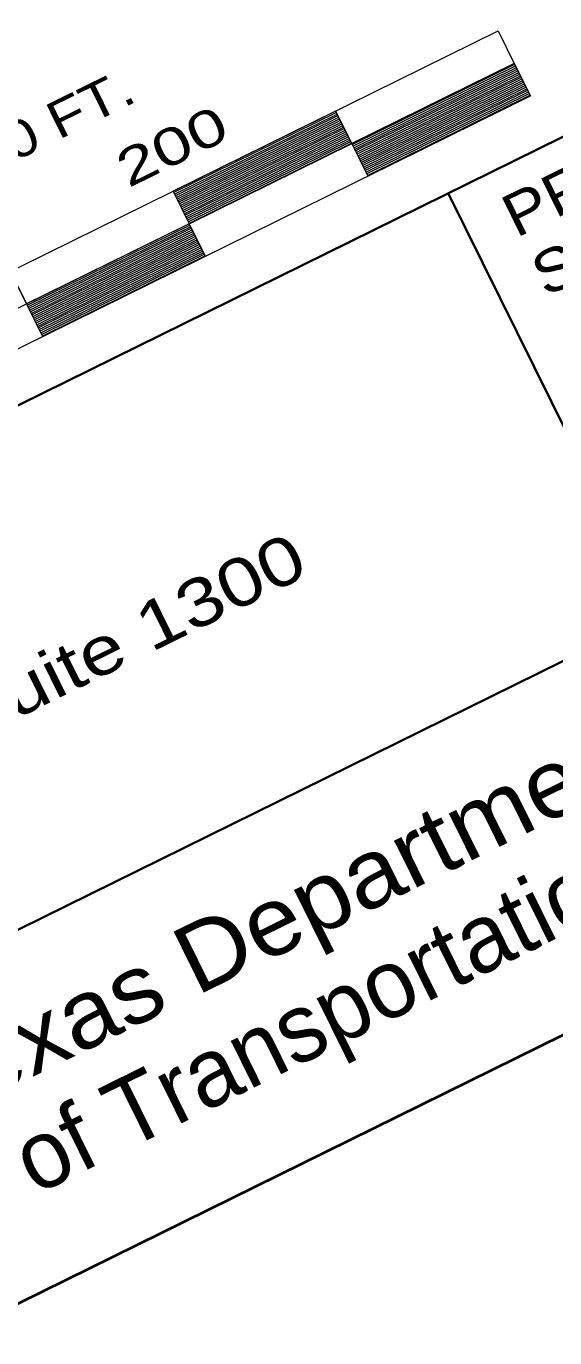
# Model space of a CAD drawing. Extents: x 2356606 to 2371222, y 6973096 to 6982644.
# Drawn here: x 2358383.7 to 2358529.4, y 6973288.2 to 6973650.2 of the extents above; entities that cross this region are included whole.
import ezdxf
from ezdxf.enums import TextEntityAlignment as Align

# ---------------------------------------------------------------- set-up
doc = ezdxf.new("R2010")
doc.units = 0
doc.header["$LTSCALE"] = 2
doc.layers.add('62', color=7, linetype='Continuous', lineweight=13)
doc.layers.add('63', color=7, linetype='Continuous', lineweight=13)

msp = doc.modelspace()

# ---------------------------------------------------------------- linework, layer by layer
at = {"layer": '62', "lineweight": 40}
msp.add_line((2370869.698, 6979460.986), (2358244.847, 6973230.201), dxfattribs=at)
at = {"layer": '62', "lineweight": 35}
for p, q in [((2358728.863, 6973716.998), (2358145.069, 6973428.875)), ((2358597.83, 6973405.896), (2358500.028, 6973604.06)), ((2358557.461, 6973487.691), (2358202.501, 6973312.506))]:
    msp.add_line(p, q, dxfattribs=at)
at = {"layer": '62'}
for p, q in [((2358155.076, 6973471.825), (2358513.803, 6973648.869)), ((2358513.803, 6973648.869), (2358518.229, 6973639.901)), ((2358159.503, 6973462.857), (2358518.229, 6973639.901)), ((2358473.506, 6973617.531), (2358518.347, 6973639.66)), ((2358473.728, 6973617.082), (2358518.568, 6973639.212)), ((2358473.948, 6973616.633), (2358518.79, 6973638.764)), ((2358474.169, 6973616.185), (2358519.011, 6973638.315)), ((2358474.39, 6973615.738), (2358519.232, 6973637.867)), ((2358518.229, 6973639.901), (2358522.655, 6973630.932)), ((2358474.612, 6973615.288), (2358519.453, 6973637.419)), ((2358474.833, 6973614.84), (2358519.674, 6973636.971)), ((2358475.054, 6973614.392), (2358519.896, 6973636.523)), ((2358475.277, 6973613.944), (2358520.117, 6973636.074)), ((2358475.498, 6973613.495), (2358520.338, 6973635.626)), ((2358475.719, 6973613.047), (2358520.56, 6973635.177)), ((2358475.94, 6973612.598), (2358520.782, 6973634.729)), ((2358476.16, 6973612.149), (2358521.003, 6973634.281)), ((2358476.382, 6973611.701), (2358521.223, 6973633.832)), ((2358476.604, 6973611.252), (2358521.445, 6973633.384)), ((2358476.825, 6973610.804), (2358521.666, 6973632.934)), ((2358477.046, 6973610.355), (2358521.888, 6973632.486)), ((2358477.268, 6973609.907), (2358522.11, 6973632.038)), ((2358477.49, 6973609.459), (2358522.33, 6973631.589)), ((2358477.711, 6973609.011), (2358522.552, 6973631.141)), ((2358424.295, 6973604.257), (2358469.134, 6973626.387)), ((2358424.516, 6973603.808), (2358469.357, 6973625.938)), ((2358424.738, 6973603.36), (2358469.577, 6973625.489)), ((2358424.958, 6973602.912), (2358469.799, 6973625.042)), ((2358425.179, 6973602.463), (2358470.02, 6973624.592)), ((2358425.401, 6973602.014), (2358470.241, 6973624.144)), ((2358425.623, 6973601.566), (2358470.463, 6973623.696)), ((2358425.843, 6973601.117), (2358470.684, 6973623.248)), ((2358468.961, 6973626.738), (2358473.387, 6973617.77)), ((2358426.065, 6973600.669), (2358470.905, 6973622.799)), ((2358426.287, 6973600.221), (2358471.127, 6973622.35)), ((2358426.507, 6973599.772), (2358471.349, 6973621.902)), ((2358426.729, 6973599.324), (2358471.57, 6973621.455)), ((2358426.95, 6973598.876), (2358471.79, 6973621.006)), ((2358427.172, 6973598.428), (2358472.011, 6973620.558)), ((2358427.392, 6973597.979), (2358472.233, 6973620.109)), ((2358427.614, 6973597.531), (2358472.455, 6973619.661)), ((2358427.836, 6973597.083), (2358472.676, 6973619.214)), ((2358428.056, 6973596.634), (2358472.896, 6973618.764)), ((2358428.278, 6973596.186), (2358473.119, 6973618.316)), ((2358428.5, 6973595.738), (2358473.339, 6973617.867)), ((2358473.387, 6973617.77), (2358477.813, 6973608.801)), ((2358424.122, 6973604.608), (2358428.548, 6973595.64)), ((2358383.879, 6973573.158), (2358428.719, 6973595.288)), ((2358384.101, 6973572.71), (2358428.941, 6973594.84)), ((2358384.321, 6973572.261), (2358429.163, 6973594.392)), ((2358428.548, 6973595.64), (2358432.973, 6973586.672)), ((2358384.543, 6973571.813), (2358429.385, 6973593.944)), ((2358384.765, 6973571.365), (2358429.605, 6973593.495)), ((2358384.985, 6973570.916), (2358429.826, 6973593.048)), ((2358385.206, 6973570.468), (2358430.048, 6973592.6)), ((2358385.428, 6973570.019), (2358430.269, 6973592.151)), ((2358385.649, 6973569.571), (2358430.491, 6973591.703)), ((2358385.871, 6973569.123), (2358430.712, 6973591.253)), ((2358386.092, 6973568.674), (2358430.932, 6973590.806)), ((2358386.314, 6973568.226), (2358431.155, 6973590.358)), ((2358386.535, 6973567.777), (2358431.375, 6973589.908)), ((2358386.757, 6973567.328), (2358431.598, 6973589.459)), ((2358386.977, 6973566.88), (2358431.818, 6973589.011)), ((2358387.198, 6973566.432), (2358432.04, 6973588.562)), ((2358387.42, 6973565.983), (2358432.261, 6973588.115)), ((2358387.641, 6973565.535), (2358432.482, 6973587.666)), ((2358387.863, 6973565.087), (2358432.704, 6973587.218)), ((2358388.084, 6973564.64), (2358432.925, 6973586.769)), ((2358379.28, 6973582.477), (2358383.706, 6973573.509)), ((2358383.706, 6973573.509), (2358388.132, 6973564.54))]:
    msp.add_line(p, q, dxfattribs=at)
for points in [[(2358477.813, 6973608.801), (2358522.655, 6973630.932), (2358518.229, 6973639.901), (2358473.387, 6973617.77)], [(2358428.548, 6973595.64), (2358473.387, 6973617.77), (2358468.961, 6973626.738), (2358424.122, 6973604.608)], [(2358388.132, 6973564.54), (2358432.973, 6973586.672), (2358428.548, 6973595.64), (2358383.706, 6973573.509)], [(2358338.865, 6973551.378), (2358383.706, 6973573.509), (2358379.28, 6973582.477), (2358334.439, 6973560.347)]]:
    msp.add_lwpolyline(points, close=True, dxfattribs=at)
at = {"layer": '63', "lineweight": 40}
msp.add_line((2370869.698, 6979460.986), (2358244.847, 6973230.201), dxfattribs=at)
at = {"layer": '63'}
for p, q in [((2358155.076, 6973471.825), (2358513.803, 6973648.869)), ((2358513.803, 6973648.869), (2358518.229, 6973639.901)), ((2358159.503, 6973462.857), (2358518.229, 6973639.901)), ((2358473.506, 6973617.531), (2358518.347, 6973639.66)), ((2358473.728, 6973617.082), (2358518.568, 6973639.212)), ((2358473.948, 6973616.633), (2358518.79, 6973638.764)), ((2358474.169, 6973616.185), (2358519.011, 6973638.315)), ((2358474.39, 6973615.738), (2358519.232, 6973637.867)), ((2358518.229, 6973639.901), (2358522.655, 6973630.932)), ((2358474.612, 6973615.288), (2358519.453, 6973637.419)), ((2358474.833, 6973614.84), (2358519.674, 6973636.971)), ((2358475.054, 6973614.392), (2358519.896, 6973636.523)), ((2358475.277, 6973613.944), (2358520.117, 6973636.074)), ((2358475.498, 6973613.495), (2358520.338, 6973635.626)), ((2358475.719, 6973613.047), (2358520.56, 6973635.177)), ((2358475.94, 6973612.598), (2358520.782, 6973634.729)), ((2358476.16, 6973612.149), (2358521.003, 6973634.281)), ((2358163.928, 6973453.889), (2358522.655, 6973630.932)), ((2358476.382, 6973611.701), (2358521.223, 6973633.832)), ((2358476.604, 6973611.252), (2358521.445, 6973633.384)), ((2358476.825, 6973610.804), (2358521.666, 6973632.934)), ((2358477.046, 6973610.355), (2358521.888, 6973632.486)), ((2358477.268, 6973609.907), (2358522.11, 6973632.038)), ((2358477.49, 6973609.459), (2358522.33, 6973631.589)), ((2358477.711, 6973609.011), (2358522.552, 6973631.141)), ((2358424.295, 6973604.257), (2358469.134, 6973626.387)), ((2358424.516, 6973603.808), (2358469.357, 6973625.938)), ((2358424.738, 6973603.36), (2358469.577, 6973625.489)), ((2358424.958, 6973602.912), (2358469.799, 6973625.042)), ((2358425.179, 6973602.463), (2358470.02, 6973624.592)), ((2358425.401, 6973602.014), (2358470.241, 6973624.144)), ((2358425.623, 6973601.566), (2358470.463, 6973623.696)), ((2358425.843, 6973601.117), (2358470.684, 6973623.248)), ((2358468.961, 6973626.738), (2358473.387, 6973617.77)), ((2358426.065, 6973600.669), (2358470.905, 6973622.799)), ((2358426.287, 6973600.221), (2358471.127, 6973622.35)), ((2358426.507, 6973599.772), (2358471.349, 6973621.902)), ((2358426.729, 6973599.324), (2358471.57, 6973621.455)), ((2358426.95, 6973598.876), (2358471.79, 6973621.006)), ((2358427.172, 6973598.428), (2358472.011, 6973620.558)), ((2358427.392, 6973597.979), (2358472.233, 6973620.109)), ((2358427.614, 6973597.531), (2358472.455, 6973619.661)), ((2358427.836, 6973597.083), (2358472.676, 6973619.214)), ((2358428.056, 6973596.634), (2358472.896, 6973618.764)), ((2358428.278, 6973596.186), (2358473.119, 6973618.316)), ((2358428.5, 6973595.738), (2358473.339, 6973617.867)), ((2358473.387, 6973617.77), (2358477.813, 6973608.801)), ((2358424.122, 6973604.608), (2358428.548, 6973595.64)), ((2358383.879, 6973573.158), (2358428.719, 6973595.288)), ((2358384.101, 6973572.71), (2358428.941, 6973594.84)), ((2358384.321, 6973572.261), (2358429.163, 6973594.392)), ((2358428.548, 6973595.64), (2358432.973, 6973586.672)), ((2358384.543, 6973571.813), (2358429.385, 6973593.944)), ((2358384.765, 6973571.365), (2358429.605, 6973593.495)), ((2358384.985, 6973570.916), (2358429.826, 6973593.048)), ((2358385.206, 6973570.468), (2358430.048, 6973592.6)), ((2358385.428, 6973570.019), (2358430.269, 6973592.151)), ((2358385.649, 6973569.571), (2358430.491, 6973591.703)), ((2358385.871, 6973569.123), (2358430.712, 6973591.253)), ((2358386.092, 6973568.674), (2358430.932, 6973590.806)), ((2358386.314, 6973568.226), (2358431.155, 6973590.358)), ((2358386.535, 6973567.777), (2358431.375, 6973589.908)), ((2358386.757, 6973567.328), (2358431.598, 6973589.459)), ((2358386.977, 6973566.88), (2358431.818, 6973589.011)), ((2358387.198, 6973566.432), (2358432.04, 6973588.562)), ((2358387.42, 6973565.983), (2358432.261, 6973588.115)), ((2358387.641, 6973565.535), (2358432.482, 6973587.666)), ((2358387.863, 6973565.087), (2358432.704, 6973587.218)), ((2358388.084, 6973564.64), (2358432.925, 6973586.769)), ((2358379.28, 6973582.477), (2358383.706, 6973573.509)), ((2358383.706, 6973573.509), (2358388.132, 6973564.54))]:
    msp.add_line(p, q, dxfattribs=at)
for points in [[(2358477.813, 6973608.801), (2358522.655, 6973630.932), (2358518.229, 6973639.901), (2358473.387, 6973617.77)], [(2358428.548, 6973595.64), (2358473.387, 6973617.77), (2358468.961, 6973626.738), (2358424.122, 6973604.608)], [(2358388.132, 6973564.54), (2358432.973, 6973586.672), (2358428.548, 6973595.64), (2358383.706, 6973573.509)], [(2358338.865, 6973551.378), (2358383.706, 6973573.509), (2358379.28, 6973582.477), (2358334.439, 6973560.347)]]:
    msp.add_lwpolyline(points, close=True, dxfattribs=at)

# ---------------------------------------------------------------- texts
at = {"layer": '62'}
for s, height, width, p in [('DIRECT CONNECTOR & RAMP DESIGN SPEED = 50 MPH', 10.2, 1.2, (2358381.426, 6973718.525)), ('FRONTAGE ROAD DESIGN SPEED VARIABLE 35 TO 40 MPH', 10.2, 1.25, (2358399.194, 6973684.505)), ('RAMP DESIGN SPEED VARIABLE 40 TO 50 MPH', 10.2, 1.25, (2358390.532, 6973700.074)), ('SCALE:  1 INCH = 100 FT.', 10.2, 1.2, (2358326.677, 6973586.227)), ('200', 10.2, 1.4, (2358426.095, 6973612.487)), ('Texas Department', 18.76, 1.1, (2358458.09, 6973396.009))]:
    msp.add_text(s, height=height, rotation=26.268, dxfattribs=dict(at, width=width)).set_placement(p, align=Align.CENTER)
for s, height, width, p in [('PRELIMINARY PLAN', 11.74, 1.15, (2358518.728, 6973591.634)), ('SUBMITTAL FOR', 11.74, 1.15, (2358526.802, 6973575.276)), ('3010 LBJ Freeway, Suite 1300', 13.22, 1.25, (2358191.148, 6973365.269))]:
    msp.add_text(s, height=height, rotation=26.268, dxfattribs=dict(at, width=width)).set_placement(p)
msp.add_text('of Transportation', height=18.76, rotation=26.268, dxfattribs=at).set_placement((2358471.15, 6973369.388), align=Align.CENTER)
at = {"layer": '63'}
for s, height, width, p in [('DIRECT CONNECTOR & RAMP DESIGN SPEED = 50 MPH', 10.2, 1.2, (2358381.426, 6973718.525)), ('200', 10.2, 1.4, (2358426.095, 6973612.487)), ('Texas Department', 18.76, 1.1, (2358458.09, 6973396.009))]:
    msp.add_text(s, height=height, rotation=26.268, dxfattribs=dict(at, width=width)).set_placement(p, align=Align.CENTER)
msp.add_text('of Transportation', height=18.76, rotation=26.268, dxfattribs=at).set_placement((2358471.15, 6973369.388), align=Align.CENTER)

doc.saveas('drawing.dxf')
